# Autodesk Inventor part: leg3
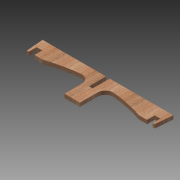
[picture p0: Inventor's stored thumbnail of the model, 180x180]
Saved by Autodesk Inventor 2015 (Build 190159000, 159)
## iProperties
Created: 2015-04
Part Number: leg3
Material: Wood (Birch)
Document SubType Name: Modeling
Designer: sungeun
Density: 0.55 g/cm^3
Appearance: Birch - Natural Polished
Author: sungeun
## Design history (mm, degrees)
sketch "Sketch1"
  geometry: L1 (-410.376, 0)-(-420, 110); L2 (-420, 110)-(0, 110); L3 (-410.376, 0)-(-310.376, 0); L4 (0, 110)-(0, 120); L5 (420, 110)-(0, 110); L6 (410.376, 0)-(420, 110); L7 (410.376, 0)-(310.376, 0); L8 (-50, 110)-(0, 110); L9 (50, 48.135)-(50, -120); L10 (50, -120)-(-50, -120); L11 (-50, -120)-(-50, 48.135); A1 r 1000 centre (0, -950.614) between (310.376, 0) and (50, 48.135); A2 r 1000 centre (0, -950.614) between (-50, 48.135) and (-310.376, 0); 2 further points
  constraints: 22 end point, 4 point on circle, 3 horizontal, 3 symmetric about line, 2 centre point, 2 parallel, 2 vertical alignment, 1 horizontal alignment, 1 midpoint, 1 perpendicular, 1 point on line, 1 vertical
  dimensions: "height" = 110 distance from line of point (0, 0) L2; "d2" = 85 deg angle of L2 L1; "d3" = 100 distance of L1.start L3.end; "d8" = 420 distance of L2.end L1.end; "d21" = 230 distance of L10.end L8.start; "d22" = 100 distance of L9.end L10.end
extrude "Extrusion1" new body sketch "Sketch1" distance "d6" = 24 (= 2 x thickness); taper "d7" = 0 deg
sketch "Sketch2"
  geometry: L1 (-397.746, 50)-(-361.746, 50); L2 (-361.746, 50)-(-361.746, -10); L3 (-361.746, -10)-(-397.746, -10); L4 (-397.746, -10)-(-397.746, 50); L5 (-410.376, 0)-(-310.376, 0) reference; L6 (420, 110)-(-420, 110) reference; L7 (0, 110)-(0, 0); L8 (397.746, 50)-(361.746, 50); L9 (361.746, 50)-(361.746, -10); L10 (397.746, -10)-(397.746, 50); L11 (361.746, -10)-(397.746, -10); 2 further points
  constraints: 18 end point, 4 symmetric about line, 3 midpoint, 2 parallel, 1 horizontal, 1 perpendicular, 1 vertical
  dimensions: "d10" = 60 distance between parallel lines of L3 L1; "d11" = 36 distance of L1.start L1.end (= 3 x thickness); "d12" = 60 distance between parallel lines of L6 L1; "d20" = 379.8775 distance of L7.end point (-379.746, -10)
extrude "Extrusion2" cut sketch "Sketch2" stored distance "d13" = 10; taper "d14" = 0 deg
sketch "Sketch3"
  geometry: L1 (420, 110)-(-420, 110) reference; L2 (-12, 110)-(12, 110); L3 (12, 110)-(12, 0); L4 (12, 0)-(-12, 0); L5 (-12, 0)-(-12, 110); 2 further points
  constraints: 8 end point, 2 parallel, 1 coincident, 1 horizontal, 1 midpoint, 1 perpendicular, 1 point on line
  dimensions: "d15" = 110 distance of L2.end L3.end; "d16" = 24 distance of L3.end L4.end (= 2 x thickness)
extrude "Extrusion3" cut sketch "Sketch3" stored distance "d17" = 10; taper "d18" = 0 deg
fillet "Fillet1" dims "d23" = 50
body "Solid1"
other parameters: "thickness" = 12 [user parameter; used in 3 equation terms]
